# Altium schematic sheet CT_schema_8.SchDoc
size 146 x 119 mm
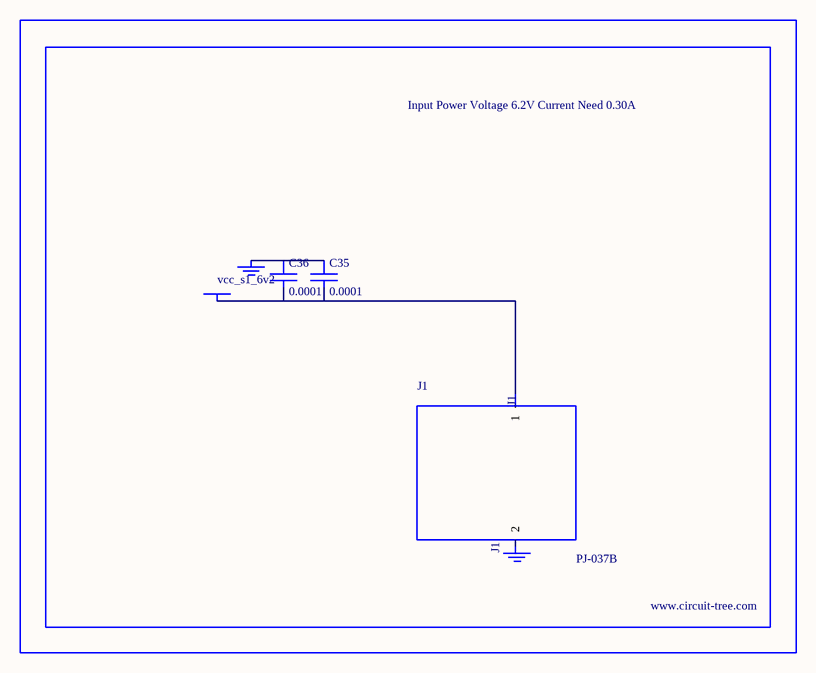
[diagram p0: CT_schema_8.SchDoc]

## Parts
BORDER7  (no value)
C35  0.0001  [EXV-9H]
C36  0.0001  [EXV-9H]
GND_INSTANCE_7_0  (no value)
GND_INSTANCE_7_1  (no value)
J1  PJ-037B  [PJ-037B_PACKAGE]
POWER_INSTANCE_7_0  vcc_s1_6v2

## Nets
NetC35_1: C35.1 C36.1 GND_INSTANCE_7_0.0(GND)
NetC35_2: C35.2 C36.2 J1.1 POWER_INSTANCE_7_0.0(PWR)

Not connected (* = marked no-connect by the designer): GND_INSTANCE_7_1 0(GND); J1 2

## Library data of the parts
BORDER7 = BORDER_PAGE7
C35 C36 = EDK107M035A9HAA
GND_INSTANCE_7_0 GND_INSTANCE_7_1 = GND
POWER_INSTANCE_7_0 = PWR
